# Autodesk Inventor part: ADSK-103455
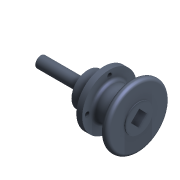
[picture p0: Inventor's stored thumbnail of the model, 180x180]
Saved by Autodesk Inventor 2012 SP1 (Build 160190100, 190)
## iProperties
Shininess: 0.0
Created: 2000-03
Part Number: ADSK-103455
Document SubType Name: Modeling
Stock Number: ADSK-103455
Density: 1 g/cm^3
Material: Default
Density: 0.0
Volume: 0.0
Area: 0.0
PropertySet Name: Model Information
Control State: 0
Checked Out: False
Master: False
Author: gao
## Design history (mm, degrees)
node "Revolution1" dims "d16" = 360 deg
  sketch "Sketch1"
    geometry: L1 (-154.196, -19.878)-(-154.196, -5.59); L2 (-154.196, -5.59)-(-34.196, -5.59); L3 (-34.196, -5.59)-(-34.196, -4.338); L4 (-34.196, -4.338)-(-33.205, -4.338); L5 (-33.205, -4.338)-(-33.205, 22.616); L6 (-33.205, 22.616)-(2.799, 22.616); L7 (2.799, 22.616)-(2.799, 25.122); L8 (2.799, 25.122)-(6.8, 25.122) reference; L9 (6.8, 25.122)-(6.8, 50.122) reference; L10 (6.8, 50.122)-(21.811, 50.122); L11 (21.811, 50.122)-(21.811, 22.104); L12 (21.811, 22.104)-(77.793, 22.104) reference; L13 (77.793, 22.104)-(77.793, 60.119); L14 (77.793, 60.119)-(95.776, 60.119); L15 (95.776, 60.119)-(95.776, 15.752); L16 (95.776, 15.752)-(97.808, 15.752); L17 (97.808, 15.752)-(97.808, 3.378); L18 (-154.196, -19.878)-(97.808, -19.878); L19 (97.808, -19.878)-(97.808, 3.378)
    constraints: 38 end point, 15 parallel, 3 perpendicular, 2 horizontal, 2 vertical
    dimensions: "d0" = 120 distance of L1.end L2.end; "d1" = 0.9906 distance of L3.end L4.end; "d3" = 4.0005 distance of L7.end L8.end; "d4" = 15.0114 distance of L9.end L10.end; "d5" = 17.9832 distance of L13.end L14.end; "d6" = 91.0082 distance between parallel lines of L17 L9; "d7" = 2.032 distance of L15.end L16.end; "d9" = 14.2875 distance of L1.start L1.end; "d11" = 42.4942 distance from line of L1.start L6; "d12" = 69.99986 distance from line of L1.start L10; "d13" = 44.99991 distance from line of L1.start L8; "d14" = 79.9973 distance from line of L14 L1.start; "d15" = 15.5398 distance from line of L18 L4.end; "d50" = 36.0045 distance of L5.end L6.end
node "Fillet1" dims "d17" = 7.9375
node "Hole2" dims "d33" = 11, "d34" = 9.525, "d35" = 6.35, "d36" = 60 deg, "d37" = 25.4, "d38" = 118 deg
  sketch "Sketch4" dims "d32" = 115
    geometry: C1 r 45 at (0, 0) reference; 2 further points
    constraints: 1 coincident, 1 vertical alignment, 2 other
node "Circular Pattern1" dims "d39" = 40, "d41" = 90 deg
workaxis "Work Axis1"
workplane "Work Plane2"
node "Extrusion2" dims "d48" = 22, "d49" = 0
  sketch "Sketch5"
    geometry: L1 (-21.212, 0.21)-(-0.21, -21.212); L2 (-0.21, -21.212)-(21.212, -0.21); L3 (21.212, -0.21)-(0.21, 21.212); L4 (0.21, 21.212)-(-21.212, 0.21); C1 r 35.63 at (0, 0) reference
    constraints: 8 end point, 2 parallel, 1 perpendicular
    dimensions: "d43" = 15 distance from line of L4 C1.centre; "d44" = 30 distance of L1.start L1.end; "d45" = 15 distance from line of L1 C1.centre (= d43); "d47" = 30 distance of L1.end L2.end (= d44)
workplane "Work Plane3"
  workaxis "Work Axis2"
  workaxis "Work Axis3"
body "Solid1"
other parameters: "d42" = 45 deg
